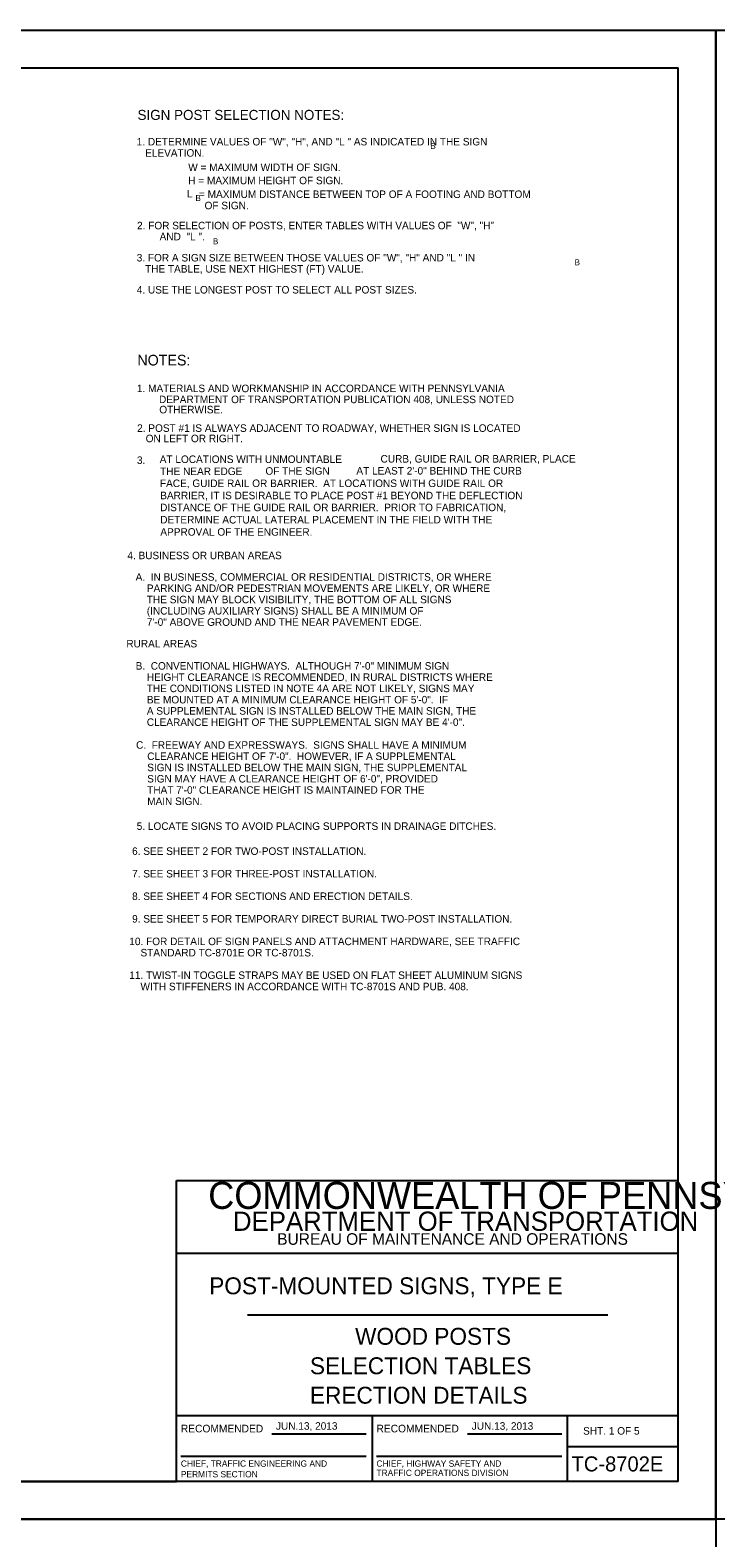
# Model space of a CAD drawing. Extents: x -2340 to 628, y -879 to 309.
# Drawn here: x -1391 to -1117, y -292 to 309 of the extents above; entities that cross this region are included whole.
import ezdxf

# ---------------------------------------------------------------- set-up
doc = ezdxf.new("R2010")
doc.units = 0
for name, color, linetype in [('Level 1', 7, 'Continuous'), ('Level 2', 7, 'Continuous'), ('Level 4', 7, 'Continuous'), ('PLT-BNDY', 7, 'Continuous')]:
    doc.layers.add(name, color=color, linetype=linetype)

msp = doc.modelspace()

# ---------------------------------------------------------------- linework, layer by layer
at = {"layer": 'Level 1'}
for p, q in [((-1918.39, 294.44), (-1132.39, 294.44)), ((-1132.39, -269.56), (-1132.39, 294.44)), ((-1332.39, -269.56), (-1332.39, -149.56)), ((-1332.39, -149.56), (-1132.39, -149.56)), ((-1132.39, -178.56), (-1332.39, -178.56)), ((-1304.14, -203.06), (-1160.51, -203.06)), ((-1332.39, -243.19), (-1132.39, -243.19)), ((-1254.39, -243.19), (-1254.39, -269.56)), ((-1176.51, -269.56), (-1176.51, -243.19)), ((-1294.45, -250.62), (-1256.83, -250.62)), ((-1216.45, -250.62), (-1178.83, -250.62)), ((-1176.51, -255.56), (-1132.39, -255.56)), ((-1330.7, -259.51), (-1256.83, -259.51)), ((-1252.7, -259.51), (-1178.83, -259.51)), ((-1132.39, -269.56), (-1918.39, -269.56)), ((-1918.39, -269.56), (-1332.39, -269.56))]:
    msp.add_line(p, q, dxfattribs=at)
at = {"layer": 'PLT-BNDY'}
for points in [[(-1958.39, 309.44), (-1117.39, 309.44), (-1117.39, -284.56), (-1958.39, -284.56)], [(-1117.39, 309.44), (-276.39, 309.44), (-276.39, -284.56), (-1117.39, -284.56)], [(-1958.39, -284.56), (-1117.39, -284.56), (-1117.39, -878.56), (-1958.39, -878.56)]]:
    msp.add_lwpolyline(points, close=True, dxfattribs=at)

# ---------------------------------------------------------------- texts
at = {"layer": 'Level 1'}
for s, height, p in [('1. DETERMINE VALUES OF "W", "H", AND "L " AS INDICATED IN THE SIGN', 3, (-1348.3, 263.45)), ('   ELEVATION.', 3, (-1348.3, 258.95)), ('B', 2.4, (-1231.21, 262.07)), ('W = MAXIMUM WIDTH OF SIGN.', 3, (-1327.76, 253.21)), ('H = MAXIMUM HEIGHT OF SIGN.', 3, (-1327.76, 247.96)), ('L', 3, (-1328.26, 242.71)), ('B', 2.4, (-1324.87, 241.22)), (' = MAXIMUM DISTANCE BETWEEN TOP OF A FOOTING AND BOTTOM', 3, (-1324.59, 242.48)), ('   OF SIGN.', 3, (-1324.59, 237.98)), ('2. FOR SELECTION OF POSTS, ENTER TABLES WITH VALUES OF  "W", "H" ', 3, (-1348.18, 229.99)), ('AND  "L ".', 3, (-1339.17, 225.58)), ('B', 2.4, (-1317.91, 224.01)), ('3. FOR A SIGN SIZE BETWEEN THOSE VALUES OF "W", "H" AND "L " IN ', 3, (-1348.31, 217.15)), ('B', 2.4, (-1173.69, 215.62)), ('   THE TABLE, USE NEXT HIGHEST (FT) VALUE.', 3, (-1348.34, 212.7)), ('4. USE THE LONGEST POST TO SELECT ALL POST SIZES.', 3, (-1348.27, 204.37)), ('1. MATERIALS AND WORKMANSHIP IN ACCORDANCE WITH PENNSYLVANIA', 3, (-1348.23, 165.01)), ('DEPARTMENT OF TRANSPORTATION PUBLICATION 408, UNLESS NOTED', 3, (-1339.41, 160.63)), ('OTHERWISE.', 3, (-1339.31, 156.56)), ('2. POST #1 IS ALWAYS ADJACENT TO ROADWAY, WHETHER SIGN IS LOCATED', 3, (-1348.13, 149.18)), ('   ON LEFT OR RIGHT.', 3, (-1348.08, 145.04)), ('3.', 3, (-1348.21, 136.37)), ('AT LOCATIONS WITH UNMOUNTABLE', 3, (-1339.13, 136.76)), (' CURB, GUIDE RAIL OR BARRIER, PLACE ', 3, (-1252.19, 136.92)), ('THE NEAR EDGE', 3, (-1338.96, 131.94)), ('OF THE SIGN ', 3, (-1296.98, 132.07)), ('AT LEAST 2\'-0" BEHIND THE CURB', 3, (-1260.71, 132.15)), ('FACE, GUIDE RAIL OR BARRIER.  AT LOCATIONS WITH GUIDE RAIL OR', 3, (-1339.04, 127.16)), ('DISTANCE OF THE GUIDE RAIL OR BARRIER.  PRIOR TO FABRICATION,', 3, (-1338.98, 117.53)), ('BARRIER, IT IS DESIRABLE TO PLACE POST #1 BEYOND THE DEFLECTION ', 3, (-1338.92, 122.3)), ('DETERMINE ACTUAL LATERAL PLACEMENT IN THE FIELD WITH THE', 3, (-1338.92, 112.62)), ('APPROVAL OF THE ENGINEER.', 3, (-1338.88, 107.75)), ('5. LOCATE SIGNS TO AVOID PLACING SUPPORTS IN DRAINAGE DITCHES.', 3, (-1348.31, -9.62)), (' 6. SEE SHEET 2 FOR TWO-POST INSTALLATION.', 3, (-1351.26, -19.6)), (' 7. SEE SHEET 3 FOR THREE-POST INSTALLATION.', 3, (-1351.26, -28.6)), (' 8. SEE SHEET 4 FOR SECTIONS AND ERECTION DETAILS.', 3, (-1351.26, -37.6)), (' 9. SEE SHEET 5 FOR TEMPORARY DIRECT BURIAL TWO-POST INSTALLATION.', 3, (-1351.26, -46.6)), ('10. FOR DETAIL OF SIGN PANELS AND ATTACHMENT HARDWARE, SEE TRAFFIC', 3, (-1351.26, -55.6)), ('    STANDARD TC-8701E OR TC-8701S.', 3, (-1351.26, -60.1)), ('11. TWIST-IN TOGGLE STRAPS MAY BE USED ON FLAT SHEET ALUMINUM SIGNS', 3, (-1351.26, -69.1)), ('    WITH STIFFENERS IN ACCORDANCE WITH TC-8701S AND PUB. 408. ', 3, (-1351.26, -73.6)), ('COMMONWEALTH OF PENNSYLVANIA', 10.7827, (-1319.79, -160.83)), ('DEPARTMENT OF TRANSPORTATION', 7.6838, (-1309.93, -169.58)), ('BUREAU OF MAINTENANCE AND OPERATIONS', 4.6252, (-1292.29, -175.15)), ('POST-MOUNTED SIGNS, TYPE E', 6.7492, (-1319.39, -194.89)), ('WOOD POSTS', 6.75, (-1261.23, -215.04)), ('SELECTION TABLES', 6.75, (-1279.23, -226.79)), ('ERECTION DETAILS', 6.75, (-1279.23, -238.54)), ('RECOMMENDED', 3.048, (-1330.7, -249.99)), ('RECOMMENDED', 3.048, (-1252.7, -249.99)), ('SHT. 1 OF 5', 3, (-1170.3, -250.88)), ('CHIEF, TRAFFIC ENGINEERING AND', 2.5, (-1330.7, -263.68)), ('CHIEF, HIGHWAY SAFETY AND', 2.5, (-1252.7, -263.68)), ('TC-8702E', 6, (-1174.91, -265.56)), ('PERMITS SECTION', 2.5, (-1330.7, -267.93)), ('TRAFFIC OPERATIONS DIVISION', 2.5, (-1252.7, -267.38))]:
    msp.add_text(s, height=height, dxfattribs=at).set_placement(p)
at = {"layer": 'Level 2'}
for s, height, p in [('SIGN POST SELECTION NOTES:', 4.003, (-1347.98, 273.62)), ('NOTES:', 4.25, (-1348.04, 175.66)), ('JUN.13, 2013', 3, (-1292.78, -248.93)), ('JUN.13, 2013', 3, (-1214.71, -248.93))]:
    msp.add_text(s, height=height, dxfattribs=at).set_placement(p)
at = {"layer": 'Level 4'}
for s, height, p in [('  4. BUSINESS OR URBAN AREAS                                               ', 2.9895, (-1354.24, 98.37)), ('     A.  IN BUSINESS, COMMERCIAL OR RESIDENTIAL DISTRICTS, OR WHERE', 3, (-1354.31, 89.79)), ('         PARKING AND/OR PEDESTRIAN MOVEMENTS ARE LIKELY, OR WHERE', 3, (-1354.31, 85.29)), ('         THE SIGN MAY BLOCK VISIBILITY, THE BOTTOM OF ALL SIGNS', 3, (-1354.31, 80.79)), ('         (INCLUDING AUXILIARY SIGNS) SHALL BE A MINIMUM OF', 3, (-1354.31, 76.29)), ('         7\'-0" ABOVE GROUND AND THE NEAR PAVEMENT EDGE.', 3, (-1354.31, 71.79)), ('       RURAL AREAS                                                           ', 2.9895, (-1360.2, 63.18)), ('     B.  CONVENTIONAL HIGHWAYS.  ALTHOUGH 7\'-0" MINIMUM SIGN', 2.9895, (-1354.26, 54.31)), ('         THE CONDITIONS LISTED IN NOTE 4A ARE NOT LIKELY, SIGNS MAY', 2.9895, (-1354.26, 45.33)), ('         HEIGHT CLEARANCE IS RECOMMENDED, IN RURAL DISTRICTS WHERE', 2.9895, (-1354.26, 49.82)), ('         BE MOUNTED AT A MINIMUM CLEARANCE HEIGHT OF 5\'-0".  IF', 2.9895, (-1354.26, 40.84)), ('         A SUPPLEMENTAL SIGN IS INSTALLED BELOW THE MAIN SIGN, THE', 2.9895, (-1354.26, 36.35)), ('         CLEARANCE HEIGHT OF THE SUPPLEMENTAL SIGN MAY BE 4\'-0".', 2.9895, (-1354.26, 31.86)), ('     C.  FREEWAY AND EXPRESSWAYS.  SIGNS SHALL HAVE A MINIMUM', 2.9895, (-1354.11, 22.76)), ('         CLEARANCE HEIGHT OF 7\'-0".  HOWEVER, IF A SUPPLEMENTAL', 2.9895, (-1354.11, 18.27)), ('         SIGN IS INSTALLED BELOW THE MAIN SIGN, THE SUPPLEMENTAL', 2.9895, (-1354.11, 13.78)), ('         SIGN MAY HAVE A CLEARANCE HEIGHT OF 6\'-0", PROVIDED', 2.9895, (-1354.11, 9.29)), ('         THAT 7\'-0" CLEARANCE HEIGHT IS MAINTAINED FOR THE', 2.9895, (-1354.11, 4.8)), ('         MAIN SIGN.', 2.9895, (-1354.11, 0.31))]:
    msp.add_text(s, height=height, dxfattribs=at).set_placement(p)

doc.saveas('drawing.dxf')
